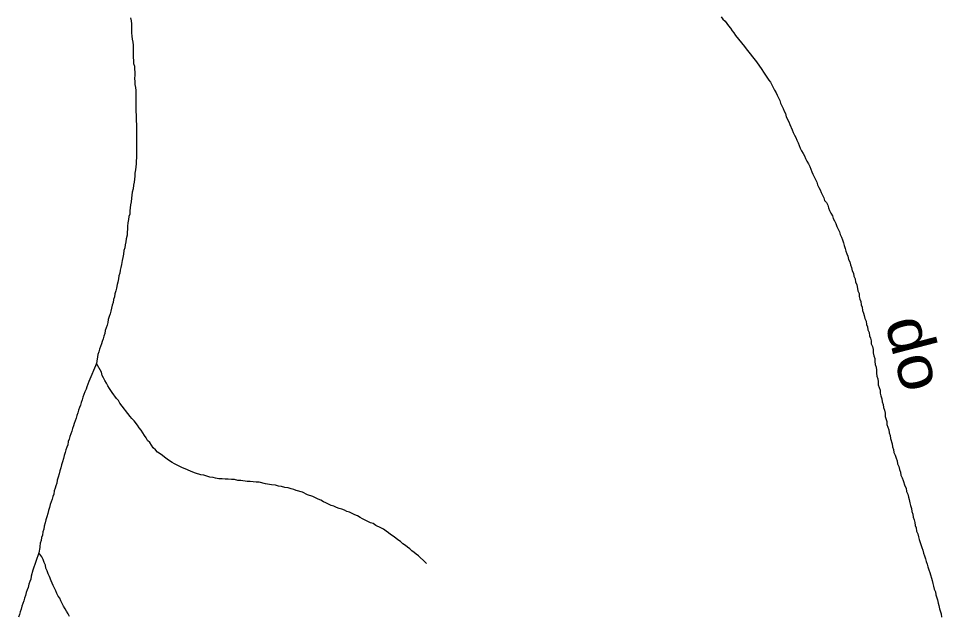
# Model space of a CAD drawing. Extents: x 652.3 to 678, y 7316.9 to 7344.9.
# Drawn here: x 668.545 to 670.229, y 7324.829 to 7325.92 of the extents above; entities that cross this region are included whole.
import ezdxf
from ezdxf.enums import TextEntityAlignment as Align

# ---------------------------------------------------------------- set-up
doc = ezdxf.new("R2010")
doc.units = 0
doc.header["$LTSCALE"] = 0.032
doc.layers.add('61', color=7, linetype='Continuous')
doc.layers.add('7', color=7, linetype='Continuous', lineweight=25)

msp = doc.modelspace()

# ---------------------------------------------------------------- linework, layer by layer
at = {"layer": '7'}
msp.add_line((668.6897, 7325.3075), (668.6873, 7325.2908), dxfattribs=at)
for points in [[(668.7494, 7325.9218), (668.7502, 7325.9162), (668.751, 7325.9107), (668.751, 7325.9051), (668.751, 7325.8995), (668.751, 7325.894), (668.7518, 7325.8884), (668.7526, 7325.8828), (668.7534, 7325.8772), (668.7541, 7325.8717), (668.7541, 7325.8661), (668.7541, 7325.8605), (668.7541, 7325.855), (668.7541, 7325.8494), (668.7549, 7325.8438), (668.7549, 7325.8383), (668.7565, 7325.8335), (668.7565, 7325.8279), (668.7573, 7325.8223), (668.7573, 7325.8168), (668.7565, 7325.8112), (668.7573, 7325.8056), (668.7573, 7325.8001), (668.7581, 7325.7945), (668.7589, 7325.7889), (668.7589, 7325.7834), (668.7589, 7325.7778), (668.7589, 7325.7722), (668.7589, 7325.7666), (668.7589, 7325.7611), (668.7589, 7325.7555), (668.7589, 7325.7499), (668.7597, 7325.7444), (668.7597, 7325.7388), (668.7597, 7325.7332), (668.7605, 7325.7277), (668.7605, 7325.7221), (668.7605, 7325.7165), (668.7605, 7325.7109), (668.7605, 7325.7054), (668.7605, 7325.6998), (668.7605, 7325.6942), (668.7605, 7325.6887), (668.7605, 7325.6831), (668.7605, 7325.6775), (668.7605, 7325.672), (668.7605, 7325.6664), (668.7597, 7325.6608), (668.7597, 7325.6553), (668.7589, 7325.6497), (668.7581, 7325.6441), (668.7573, 7325.6385), (668.7573, 7325.633), (668.7565, 7325.6274), (668.7557, 7325.6218), (668.7549, 7325.6163), (668.7541, 7325.6099)], [(669.8267, 7325.9234), (669.8299, 7325.9194), (669.8339, 7325.9154), (669.8371, 7325.9115), (669.8403, 7325.9067), (669.8434, 7325.9027), (669.8466, 7325.8979), (669.8498, 7325.894), (669.853, 7325.8892), (669.8689, 7325.8693), (669.8721, 7325.8653), (669.8912, 7325.8414), (669.9007, 7325.8271), (669.9039, 7325.8223), (669.9135, 7325.808), (669.9166, 7325.804), (669.919, 7325.7993), (669.9238, 7325.7897), (669.927, 7325.7849), (669.9286, 7325.7802), (669.9334, 7325.7706), (669.9349, 7325.7659), (669.9373, 7325.7611), (669.9397, 7325.7563), (669.9413, 7325.7515), (669.9437, 7325.7468), (669.9453, 7325.7412), (669.9501, 7325.7316), (669.9517, 7325.7269), (669.9564, 7325.7173), (669.958, 7325.7125), (669.9604, 7325.7078), (669.9628, 7325.703), (669.9644, 7325.6982), (669.9668, 7325.6934), (669.9692, 7325.6887), (669.9708, 7325.6839), (669.9731, 7325.6791), (669.9763, 7325.6743), (669.9787, 7325.6696), (669.9803, 7325.6648), (669.9827, 7325.66), (669.9859, 7325.6553), (669.9883, 7325.6505), (669.9899, 7325.6457), (669.9922, 7325.6409), (669.9938, 7325.6362), (669.9962, 7325.6314), (670.001, 7325.6218), (670.0026, 7325.6171), (670.005, 7325.6123), (670.0074, 7325.6075), (670.0089, 7325.6027), (670.0113, 7325.598), (670.0137, 7325.5932), (670.0153, 7325.5884), (670.0185, 7325.5844), (670.0209, 7325.5797), (670.0225, 7325.5749), (670.0241, 7325.5701), (670.0265, 7325.5653), (670.0296, 7325.5606), (670.0312, 7325.5558), (670.0336, 7325.551), (670.036, 7325.5462), (670.0376, 7325.5407), (670.04, 7325.5359), (670.0424, 7325.5311), (670.044, 7325.5263), (670.0463, 7325.5216)], [(668.7541, 7325.6099), (668.7526, 7325.6035), (668.7518, 7325.598), (668.751, 7325.5924), (668.7502, 7325.586), (668.7494, 7325.5805), (668.7486, 7325.5749), (668.7478, 7325.5693), (668.7478, 7325.5637), (668.7462, 7325.559), (668.7454, 7325.5534), (668.7446, 7325.5478), (668.7438, 7325.5415), (668.7438, 7325.5359), (668.743, 7325.5303), (668.743, 7325.5248), (668.7414, 7325.5184), (668.7406, 7325.5128), (668.7398, 7325.5073), (668.739, 7325.5017), (668.7374, 7325.4969), (668.7366, 7325.4905), (668.7351, 7325.4842), (668.7343, 7325.4786), (668.7327, 7325.4714), (668.7319, 7325.4659), (668.7303, 7325.4611), (668.7295, 7325.4555), (668.7279, 7325.4508), (668.7271, 7325.4452), (668.7263, 7325.4396), (668.7247, 7325.4348), (668.7239, 7325.4285), (668.7223, 7325.4237), (668.7207, 7325.4181), (668.7199, 7325.4126), (668.7183, 7325.4078), (668.7175, 7325.4022), (668.716, 7325.3974), (668.7144, 7325.3919), (668.7136, 7325.3863), (668.712, 7325.3815), (668.7104, 7325.3768), (668.7088, 7325.3712), (668.708, 7325.3656), (668.7064, 7325.3608), (668.7048, 7325.3561), (668.7032, 7325.3513), (668.7024, 7325.3457), (668.7008, 7325.341), (668.6992, 7325.3362), (668.6977, 7325.3314), (668.6961, 7325.3266), (668.6945, 7325.3219), (668.6929, 7325.3171), (668.6913, 7325.3123), (668.6897, 7325.3075)], [(670.0463, 7325.5216), (670.0479, 7325.5168), (670.0495, 7325.5112), (670.0511, 7325.5065), (670.0527, 7325.5009), (670.0543, 7325.4961), (670.0559, 7325.4913), (670.0575, 7325.4866), (670.0591, 7325.481), (670.0615, 7325.4762), (670.0623, 7325.4707), (670.0646, 7325.4659), (670.0654, 7325.4603), (670.0678, 7325.4555), (670.0686, 7325.45), (670.071, 7325.4452), (670.0718, 7325.4396), (670.0742, 7325.4348), (670.0758, 7325.4237), (670.0782, 7325.4189), (670.0782, 7325.4134), (670.0798, 7325.4086), (670.0814, 7325.4038), (670.0822, 7325.3982), (670.0837, 7325.3935), (670.0845, 7325.3879), (670.0861, 7325.3831), (670.0877, 7325.3784), (670.0885, 7325.3728), (670.0909, 7325.368), (670.0917, 7325.3624), (670.0933, 7325.3577), (670.0941, 7325.3521), (670.0965, 7325.3473), (670.0973, 7325.3417), (670.0989, 7325.337), (670.1005, 7325.3322), (670.1005, 7325.3266), (670.1028, 7325.3219), (670.1036, 7325.3163), (670.1036, 7325.3107), (670.1052, 7325.3051), (670.1068, 7325.3004), (670.1068, 7325.2948), (670.1076, 7325.2892), (670.1092, 7325.2845), (670.11, 7325.2789), (670.11, 7325.2733), (670.1108, 7325.2678), (670.1124, 7325.263), (670.1132, 7325.2574), (670.1132, 7325.2518), (670.1164, 7325.2423), (670.1164, 7325.2367), (670.118, 7325.2319), (670.1195, 7325.2264), (670.1203, 7325.2208), (670.1219, 7325.216), (670.1227, 7325.2105), (670.1243, 7325.2057), (670.1259, 7325.2001), (670.1259, 7325.1945), (670.1291, 7325.185), (670.1291, 7325.1794), (670.1323, 7325.1699), (670.1331, 7325.1643), (670.1347, 7325.1595), (670.1355, 7325.154), (670.1386, 7325.1444), (670.1394, 7325.1388), (670.141, 7325.1341), (670.1418, 7325.1285), (670.1442, 7325.1237), (670.1458, 7325.1182), (670.1474, 7325.1134), (670.1482, 7325.1078), (670.1506, 7325.103), (670.1522, 7325.0975), (670.1538, 7325.0927), (670.1546, 7325.0871), (670.1569, 7325.0824), (670.1585, 7325.0776), (670.1617, 7325.068), (670.1641, 7325.0633), (670.1649, 7325.0577), (670.1673, 7325.0529), (670.1681, 7325.0473), (670.1697, 7325.0426), (670.1705, 7325.037), (670.1721, 7325.0322), (670.1737, 7325.0267), (670.1745, 7325.0211), (670.176, 7325.0163), (670.1768, 7325.0107), (670.1784, 7325.006), (670.18, 7325.0012), (670.1808, 7324.9956), (670.1824, 7324.9909), (670.1832, 7324.9853), (670.1856, 7324.9805), (670.1864, 7324.9749)], [(668.6873, 7325.2908), (668.673, 7325.2582), (668.6698, 7325.2487), (668.6682, 7325.2439), (668.6658, 7325.2391), (668.6642, 7325.2343), (668.6626, 7325.2296), (668.6611, 7325.2248), (668.6595, 7325.22), (668.6579, 7325.2152), (668.6563, 7325.2105), (668.6547, 7325.2057), (668.6531, 7325.2009), (668.6515, 7325.1961), (668.6499, 7325.1914), (668.6483, 7325.1866), (668.6467, 7325.1818), (668.6451, 7325.177), (668.6435, 7325.1723), (668.642, 7325.1675), (668.6404, 7325.1627), (668.6388, 7325.1579), (668.6372, 7325.1532), (668.6356, 7325.1484), (668.6348, 7325.1428), (668.6332, 7325.1381), (668.6316, 7325.1333), (668.63, 7325.1285), (668.6284, 7325.1229), (668.6268, 7325.1174), (668.6252, 7325.1118), (668.6237, 7325.1062), (668.6221, 7325.1007), (668.6205, 7325.0951), (668.6189, 7325.0895), (668.6173, 7325.0839), (668.6157, 7325.0784), (668.6149, 7325.0728), (668.6133, 7325.068), (668.6117, 7325.0633), (668.6101, 7325.0585), (668.6093, 7325.0529), (668.6077, 7325.0481), (668.6062, 7325.0434)], [(668.716, 7325.2383), (668.7112, 7325.2455), (668.708, 7325.2502), (668.7056, 7325.255), (668.7024, 7325.2598), (668.7, 7325.2646), (668.6977, 7325.2693), (668.6961, 7325.2749), (668.6873, 7325.2908)], [(669.2894, 7324.9261), (669.2888, 7324.9266), (669.2865, 7324.9288), (669.2745, 7324.9399), (669.2705, 7324.9431), (669.2666, 7324.9463), (669.2626, 7324.9495), (669.2586, 7324.9527), (669.2546, 7324.9558), (669.2507, 7324.959), (669.2459, 7324.9622), (669.2419, 7324.9662), (669.2371, 7324.9694), (669.2332, 7324.9726), (669.2284, 7324.9757), (669.2236, 7324.9789), (669.2196, 7324.9821), (669.2156, 7324.9853), (669.2109, 7324.9885), (669.2061, 7324.9909), (669.1966, 7324.9956), (669.1918, 7324.9988), (669.187, 7325.0004), (669.1727, 7325.0076), (669.1679, 7325.0099), (669.1631, 7325.0131), (669.1584, 7325.0147), (669.1488, 7325.0195), (669.144, 7325.0211), (669.1393, 7325.0235), (669.1345, 7325.0251), (669.1297, 7325.0267), (669.1249, 7325.0282), (669.1202, 7325.0306), (669.1154, 7325.0322), (669.1058, 7325.037), (669.1011, 7325.0386), (669.0963, 7325.0418), (669.0915, 7325.0434), (669.082, 7325.0481), (669.0724, 7325.0513), (669.0629, 7325.0561), (669.0517, 7325.0593), (669.047, 7325.0609), (669.0422, 7325.0625), (669.0366, 7325.0641), (669.031, 7325.0648), (669.0247, 7325.0664), (669.0191, 7325.0672), (669.0135, 7325.0688), (669.0064, 7325.0696), (668.9952, 7325.0712), (668.9841, 7325.0744), (668.9785, 7325.0744), (668.973, 7325.0752), (668.9674, 7325.076), (668.9618, 7325.076), (668.9507, 7325.0776), (668.9451, 7325.0776), (668.9387, 7325.0792), (668.9332, 7325.0792), (668.9276, 7325.08), (668.922, 7325.08), (668.9165, 7325.0808), (668.9101, 7325.0808), (668.9045, 7325.0816), (668.8998, 7325.0832), (668.8942, 7325.0839), (668.883, 7325.0871), (668.8775, 7325.0879), (668.8679, 7325.0911), (668.8632, 7325.0927), (668.8584, 7325.0943), (668.8488, 7325.0991), (668.8441, 7325.1007), (668.8345, 7325.1054), (668.8297, 7325.1078), (668.825, 7325.1102), (668.8202, 7325.1134), (668.8162, 7325.1166), (668.8114, 7325.1198), (668.8075, 7325.1229), (668.8035, 7325.1261), (668.7987, 7325.1293), (668.7947, 7325.1333), (668.7907, 7325.1373), (668.7876, 7325.142), (668.7844, 7325.1468), (668.7804, 7325.1508), (668.778, 7325.1556), (668.7748, 7325.1595), (668.7685, 7325.1691), (668.7653, 7325.1739), (668.7621, 7325.1786), (668.7557, 7325.1866), (668.7518, 7325.1906), (668.7486, 7325.1945), (668.7295, 7325.2184), (668.7271, 7325.2232), (668.7239, 7325.2272), (668.716, 7325.2383)], [(668.6062, 7325.0434), (668.6046, 7325.0386), (668.603, 7325.0338), (668.6014, 7325.0282), (668.5998, 7325.0227), (668.5982, 7325.0171), (668.5966, 7325.0115), (668.595, 7325.006), (668.5934, 7325.0004), (668.5918, 7324.994), (668.591, 7324.9885), (668.5894, 7324.9837), (668.5886, 7324.9781), (668.5871, 7324.9733), (668.5863, 7324.9678), (668.5847, 7324.963), (668.5839, 7324.9574), (668.5836, 7324.9553), (668.5823, 7324.9455)], [(670.1864, 7324.9749), (670.188, 7324.9702), (670.1896, 7324.9646), (670.1928, 7324.955), (670.1943, 7324.9503), (670.1959, 7324.9447), (670.1975, 7324.9399), (670.1991, 7324.9344), (670.2007, 7324.9296), (670.2023, 7324.9248), (670.2039, 7324.92), (670.2055, 7324.9145), (670.2071, 7324.9097), (670.2118, 7324.8954), (670.2126, 7324.8898), (670.2142, 7324.885), (670.215, 7324.8795), (670.2174, 7324.8747), (670.2182, 7324.8691), (670.2214, 7324.8596), (670.2222, 7324.854), (670.2238, 7324.8492), (670.2246, 7324.8436), (670.2278, 7324.8341), (670.2286, 7324.8285)], [(668.5823, 7324.9455), (668.5711, 7324.9137), (668.568, 7324.9033), (668.5672, 7324.8978), (668.5656, 7324.893), (668.564, 7324.8882), (668.5624, 7324.8826), (668.5608, 7324.8779), (668.5592, 7324.8731), (668.5576, 7324.8675), (668.556, 7324.8627), (668.5544, 7324.858), (668.5528, 7324.8532), (668.5512, 7324.8484), (668.5497, 7324.8429), (668.5481, 7324.8381), (668.5465, 7324.8333), (668.5449, 7324.8285)], [(668.6149, 7324.8715), (668.6133, 7324.8763), (668.6085, 7324.8858), (668.6046, 7324.8946), (668.6014, 7324.9025), (668.599, 7324.9073), (668.5974, 7324.9129), (668.595, 7324.9176), (668.5942, 7324.9232), (668.5918, 7324.928), (668.5902, 7324.9336), (668.5878, 7324.9383), (668.5823, 7324.9455)], [(668.638, 7324.8293), (668.6356, 7324.8341), (668.6324, 7324.8389), (668.63, 7324.8436), (668.6268, 7324.8484), (668.6245, 7324.8532), (668.6221, 7324.858), (668.6205, 7324.8627), (668.6173, 7324.8667), (668.6149, 7324.8715)]]:
    msp.add_lwpolyline(points, dxfattribs=at)

# ---------------------------------------------------------------- texts
at = {"layer": '61', "width": 1.15}
msp.add_text('do', height=0.08, rotation=284.52, dxfattribs=at).set_placement((670.142, 7325.3003), align=Align.CENTER)

doc.saveas('drawing.dxf')
